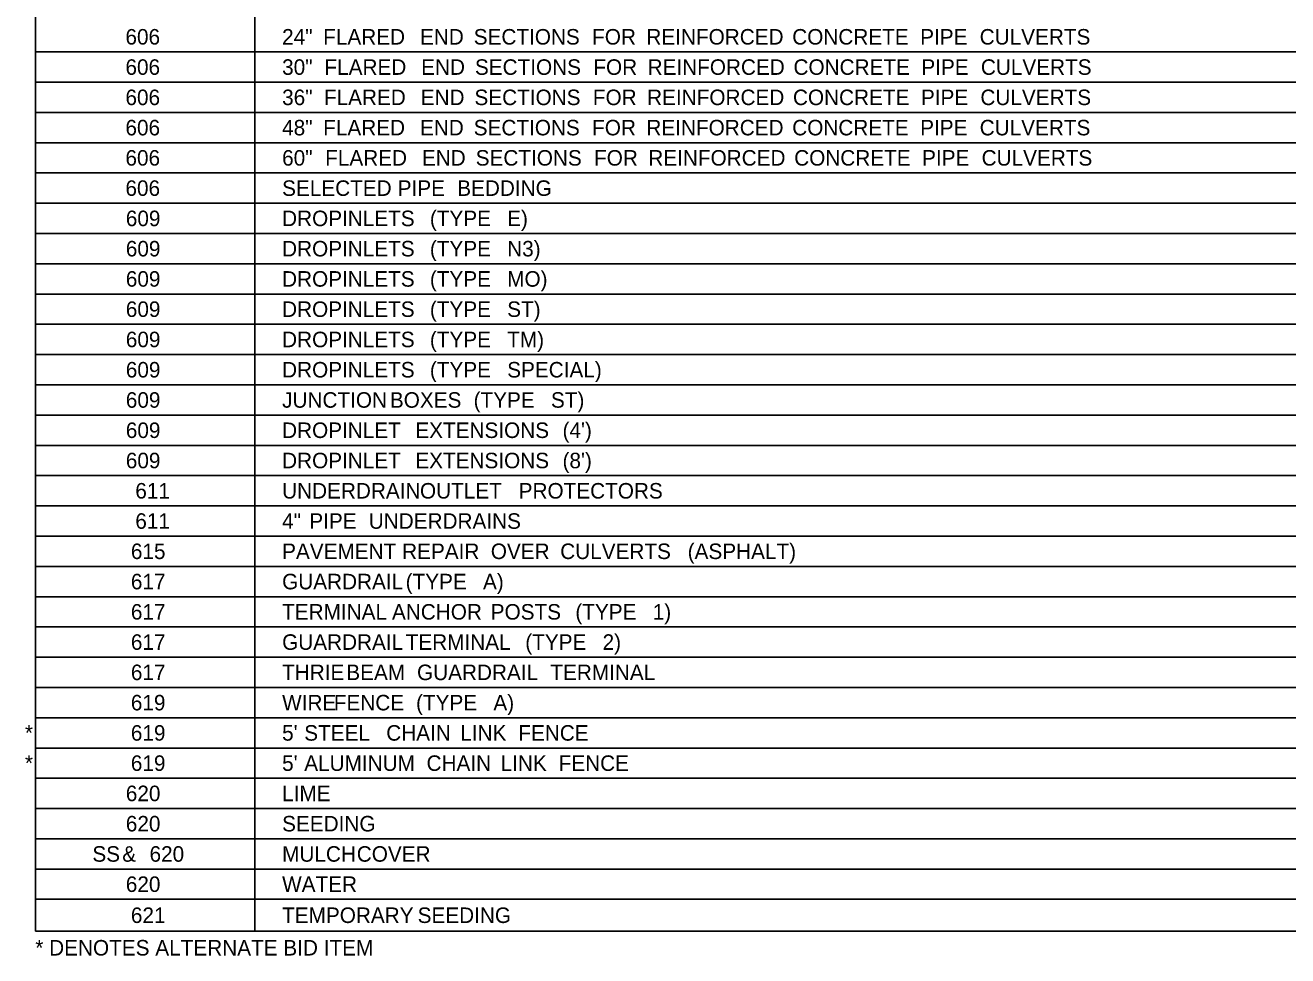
# Model space of a CAD drawing. Extents: x 1226603 to 1228117, y 151305 to 152343.
# Drawn here: x 1226603 to 1226948.8, y 151332.2 to 151587 of the extents above; entities that cross this region are included whole.
import ezdxf

# ---------------------------------------------------------------- set-up
doc = ezdxf.new("R2010")
doc.units = 0
doc.layers.add('R_Dimension', color=7, linetype='Continuous')

msp = doc.modelspace()

# ---------------------------------------------------------------- linework, layer by layer
at = {"layer": 'R_Dimension'}
for p, q in [((1226605.78, 151338.98), (1226605.78, 152334.72)), ((1226665.86, 151338.98), (1226665.86, 152334.72)), ((1226605.78, 151579.73), (1227235.63, 151579.73)), ((1226605.78, 151571.44), (1227235.63, 151571.44)), ((1226605.78, 151563.15), (1227235.63, 151563.15)), ((1226605.78, 151554.86), (1227235.63, 151554.86)), ((1226605.78, 151546.58), (1227235.63, 151546.58)), ((1226605.78, 151538.29), (1227235.63, 151538.29)), ((1226605.78, 151530), (1227235.63, 151530)), ((1226605.78, 151521.71), (1227235.63, 151521.71)), ((1226605.78, 151513.43), (1227235.63, 151513.43)), ((1226605.78, 151505.14), (1227235.63, 151505.14)), ((1226605.78, 151496.85), (1227235.63, 151496.85)), ((1226605.78, 151488.56), (1227235.63, 151488.56)), ((1226605.78, 151480.28), (1227235.63, 151480.28)), ((1226605.78, 151471.99), (1227235.63, 151471.99)), ((1226605.78, 151463.7), (1227235.63, 151463.7)), ((1226605.78, 151455.41), (1227235.63, 151455.41)), ((1226605.78, 151447.13), (1227235.63, 151447.13)), ((1226605.78, 151438.84), (1227235.63, 151438.84)), ((1226605.78, 151430.55), (1227235.63, 151430.55)), ((1226605.78, 151422.26), (1227235.63, 151422.26)), ((1226605.78, 151413.98), (1227235.63, 151413.98)), ((1226605.78, 151405.69), (1227235.63, 151405.69)), ((1226605.78, 151397.4), (1227235.63, 151397.4)), ((1226605.78, 151389.11), (1227235.63, 151389.11)), ((1226605.78, 151380.83), (1227235.63, 151380.83)), ((1226605.78, 151372.54), (1227235.63, 151372.54)), ((1226605.78, 151364.25), (1227235.63, 151364.25)), ((1226605.78, 151355.96), (1227235.63, 151355.96)), ((1226605.78, 151347.68), (1227235.63, 151347.68)), ((1226605.78, 151338.98), (1227235.63, 151338.98))]:
    msp.add_line(p, q, dxfattribs=at)

# ---------------------------------------------------------------- texts
for s, height, p in [('606', 4.25, (1226630.41, 151581.75)), ('24"', 4.25, (1226673.32, 151581.75)), (' FLARED', 4.25, (1226682.99, 151581.75)), (' END', 4.25, (1226709.5, 151581.75)), (' SECTIONS', 4.25, (1226724.22, 151581.75)), (' FOR', 4.25, (1226756.65, 151581.75)), (' REINFORCED', 4.25, (1226771.51, 151581.75)), (' CONCRETE', 4.25, (1226811.46, 151581.75)), (' PIPE', 4.25, (1226846.5, 151581.75)), (' CULVERTS', 4.25, (1226862.8, 151581.75)), ('606', 4.25, (1226630.41, 151573.46)), ('30"', 4.25, (1226673.32, 151573.46)), (' FLARED', 4.25, (1226683.33, 151573.46)), (' END', 4.25, (1226709.83, 151573.46)), (' SECTIONS', 4.25, (1226724.55, 151573.46)), (' FOR', 4.25, (1226756.98, 151573.46)), (' REINFORCED', 4.25, (1226771.84, 151573.46)), (' CONCRETE', 4.25, (1226811.8, 151573.46)), (' PIPE', 4.25, (1226846.83, 151573.46)), (' CULVERTS', 4.25, (1226863.13, 151573.46)), ('606', 4.25, (1226630.41, 151565.17)), ('36"', 4.25, (1226673.32, 151565.17)), (' FLARED', 4.25, (1226683.19, 151565.17)), (' END', 4.25, (1226709.7, 151565.17)), (' SECTIONS', 4.25, (1226724.42, 151565.17)), (' FOR', 4.25, (1226756.85, 151565.17)), (' REINFORCED', 4.25, (1226771.71, 151565.17)), (' CONCRETE', 4.25, (1226811.66, 151565.17)), (' PIPE', 4.25, (1226846.7, 151565.17)), (' CULVERTS', 4.25, (1226863, 151565.17)), ('606', 4.25, (1226630.41, 151556.88)), ('48"', 4.25, (1226673.32, 151556.88)), (' SECTIONS', 4.25, (1226724.22, 151556.88)), (' FOR', 4.25, (1226756.65, 151556.88)), (' REINFORCED', 4.25, (1226771.51, 151556.88)), (' CONCRETE', 4.25, (1226811.46, 151556.88)), (' CULVERTS', 4.25, (1226862.8, 151556.88)), (' FLARED', 4.25, (1226682.99, 151556.88)), (' END', 4.25, (1226709.5, 151556.88)), (' PIPE', 4.25, (1226846.5, 151556.88)), ('606', 4.25, (1226630.41, 151548.6)), ('60"', 4.25, (1226673.32, 151548.6)), (' FLARED', 4.25, (1226683.53, 151548.6)), (' END', 4.25, (1226710.03, 151548.6)), (' SECTIONS', 4.25, (1226724.76, 151548.6)), (' FOR', 4.25, (1226757.18, 151548.6)), (' REINFORCED', 4.25, (1226772.04, 151548.6)), (' CONCRETE', 4.25, (1226812, 151548.6)), (' PIPE', 4.25, (1226847.03, 151548.6)), (' CULVERTS', 4.25, (1226863.33, 151548.6)), ('606', 4.25, (1226630.41, 151540.31)), ('SELECTED', 4.25, (1226673.32, 151540.31)), (' PIPE', 4.25, (1226703.4, 151540.31)), (' BEDDING', 4.25, (1226719.7, 151540.31)), ('609', 4.25, (1226630.51, 151532.02)), ('DROP', 4.25, (1226673.32, 151532.02)), (' INLETS', 4.25, (1226688.14, 151532.02)), (' (TYPE', 4.25, (1226712.21, 151532.02)), (' E)', 4.25, (1226733.39, 151532.02)), ('609', 4.25, (1226630.51, 151523.73)), ('DROP', 4.25, (1226673.32, 151523.73)), (' INLETS', 4.25, (1226688.14, 151523.73)), (' (TYPE', 4.25, (1226712.21, 151523.73)), (' N3)', 4.25, (1226733.39, 151523.73)), ('609', 4.25, (1226630.51, 151515.45)), ('DROP', 4.25, (1226673.32, 151515.45)), (' INLETS', 4.25, (1226688.14, 151515.45)), (' (TYPE', 4.25, (1226712.21, 151515.45)), (' MO)', 4.25, (1226733.39, 151515.45)), ('609', 4.25, (1226630.51, 151507.16)), ('DROP', 4.25, (1226673.32, 151507.16)), (' INLETS', 4.25, (1226688.14, 151507.16)), (' (TYPE', 4.25, (1226712.21, 151507.16)), (' ST)', 4.25, (1226733.39, 151507.16)), ('609', 4.25, (1226630.51, 151498.87)), ('DROP', 4.25, (1226673.32, 151498.87)), (' INLETS', 4.25, (1226688.14, 151498.87)), (' (TYPE', 4.25, (1226712.21, 151498.87)), (' TM)', 4.25, (1226733.39, 151498.87)), ('609', 4.25, (1226630.51, 151490.58)), ('DROP', 4.25, (1226673.32, 151490.58)), (' INLETS', 4.25, (1226688.14, 151490.58)), (' (TYPE', 4.25, (1226712.21, 151490.58)), (' SPECIAL)', 4.25, (1226733.39, 151490.58)), ('609', 4.25, (1226630.51, 151482.3)), ('JUNCTION', 4.25, (1226673.32, 151482.3)), (' BOXES', 4.25, (1226701.26, 151482.3)), (' (TYPE', 4.25, (1226724.19, 151482.3)), (' ST)', 4.25, (1226745.37, 151482.3)), ('609', 4.25, (1226630.51, 151474.01)), ('DROP', 4.25, (1226673.32, 151474.01)), (' INLET', 4.25, (1226688.14, 151474.01)), (' EXTENSIONS', 4.25, (1226708.22, 151474.01)), (" (4')", 4.25, (1226748.55, 151474.01)), ('609', 4.25, (1226630.51, 151465.72)), ('DROP', 4.25, (1226673.32, 151465.72)), (' INLET', 4.25, (1226688.14, 151465.72)), (' EXTENSIONS', 4.25, (1226708.22, 151465.72)), (" (8')", 4.25, (1226748.55, 151465.72)), ('611', 4.25, (1226633.11, 151457.43)), ('UNDERDRAIN', 4.25, (1226673.32, 151457.43)), (' OUTLET', 4.25, (1226709.5, 151457.43)), (' PROTECTORS', 4.25, (1226736.53, 151457.43)), ('611', 4.25, (1226633.11, 151449.15)), ('4"', 4.25, (1226673.32, 151449.15)), (' PIPE', 4.25, (1226679.18, 151449.15)), (' UNDERDRAINS', 4.25, (1226695.47, 151449.15)), ('615', 4.25, (1226631.9, 151440.86)), ('PAVEMENT', 4.25, (1226673.32, 151440.86)), (' REPAIR', 4.25, (1226704.61, 151440.86)), (' OVER', 4.25, (1226728.9, 151440.86)), (' CULVERTS', 4.25, (1226747.91, 151440.86)), (' (ASPHALT)', 4.25, (1226782.82, 151440.86)), ('617', 4.25, (1226631.9, 151432.57)), ('GUARDRAIL', 4.25, (1226673.32, 151432.57)), (' (TYPE', 4.25, (1226705.58, 151432.57)), (' A)', 4.25, (1226726.76, 151432.57)), ('617', 4.25, (1226631.9, 151424.28)), ('TERMINAL', 4.25, (1226673.32, 151424.28)), (' ANCHOR', 4.25, (1226701.83, 151424.28)), (' POSTS', 4.25, (1226728.87, 151424.28)), (' (TYPE', 4.25, (1226752.06, 151424.28)), (' 1)', 4.25, (1226773.25, 151424.28)), ('617', 4.25, (1226631.9, 151416)), ('GUARDRAIL', 4.25, (1226673.32, 151416)), (' TERMINAL', 4.25, (1226705.58, 151416)), (' (TYPE', 4.25, (1226738.34, 151416)), (' 2)', 4.25, (1226759.52, 151416)), ('617', 4.25, (1226631.9, 151407.71)), ('THRIE', 4.25, (1226673.32, 151407.71)), (' BEAM', 4.25, (1226689.32, 151407.71)), (' GUARDRAIL', 4.25, (1226708.69, 151407.71)), (' TERMINAL', 4.25, (1226745.2, 151407.71)), ('619', 4.25, (1226631.89, 151399.42)), ('WIRE', 4.25, (1226673.32, 151399.42)), (' FENCE', 4.25, (1226685.9, 151399.42)), (' (TYPE', 4.25, (1226708.42, 151399.42)), (' A)', 4.25, (1226729.61, 151399.42)), ('*', 4.25, (1226602.87, 151391.13)), ('619', 4.25, (1226631.89, 151391.13)), ("5'", 4.25, (1226673.32, 151391.13)), (' STEEL', 4.25, (1226677.8, 151391.13)), (' CHAIN', 4.25, (1226700.26, 151391.13)), (' LINK', 4.25, (1226720.54, 151391.13)), (' FENCE', 4.25, (1226736.43, 151391.13)), ('*', 4.25, (1226602.87, 151382.85)), ('619', 4.25, (1226631.89, 151382.85)), ("5'", 4.25, (1226673.32, 151382.85)), (' ALUMINUM', 4.25, (1226677.8, 151382.85)), (' CHAIN', 4.25, (1226711.3, 151382.85)), (' LINK', 4.25, (1226731.58, 151382.85)), (' FENCE', 4.25, (1226747.48, 151382.85)), ('620', 4.25, (1226630.51, 151374.56)), ('LIME', 4.25, (1226673.32, 151374.56)), ('620', 4.25, (1226630.51, 151366.27)), ('SEEDING', 4.25, (1226673.32, 151366.27)), ('SS', 4.25, (1226621.35, 151357.98)), (' &', 4.25, (1226627.97, 151357.98)), (' 620', 4.25, (1226635.43, 151357.98)), ('MULCH', 4.25, (1226673.32, 151357.98)), (' COVER', 4.25, (1226692.19, 151357.98)), ('620', 4.25, (1226630.51, 151349.7)), ('WATER', 4.25, (1226673.32, 151349.7)), ('621', 4.25, (1226631.9, 151341.2)), ('TEMPORARY', 4.25, (1226673.32, 151341.2)), (' SEEDING', 4.25, (1226708.86, 151341.2)), ('* DENOTES ALTERNATE BID ITEM', 4.2525, (1226605.72, 151332.29))]:
    msp.add_text(s, height=height, dxfattribs=at).set_placement(p)

doc.saveas('drawing.dxf')
